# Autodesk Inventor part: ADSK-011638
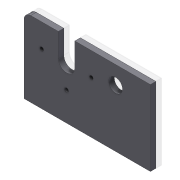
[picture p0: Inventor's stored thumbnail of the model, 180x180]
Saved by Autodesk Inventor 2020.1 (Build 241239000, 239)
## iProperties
Created: 2000-02
Part Number: ADSK-011638
Material: Pearson HRS
Document SubType Name: Modeling
Description: PLT-14,FH,CP,03,090,053,MNT,HANDWHEEL
Designer: cmcgourin
Density: 7.83 g/cm^3
Appearance: Métal - Acier
Mass: 2260.83 g
Surface Area: 675.493 cm^2
Volume: 288.739 cm^3
Control State: 0
Checked Out: False
Master: False
Shininess: 0.0
Length Units: 11269
Angle Units: 11279
Time Units: 11290
Mass Units: 11286
Length Display Precision: 3
Angle Display Precision: 2
Compacted: True
Cutlength: 5.38
Material Desc: FLAT,HRS,0.375X09.000
Material_Number: A084416
Dimensions: 229x136,5x10 mm
Mass: 4,984 lb
Density: 0.0
Volumn: 0.0
Area: 0.0
PropertySet Name: Model Information
Author: cmcgourin
Revision Number: -
Title: PLT-14,FH,CP,03,090,053,MNT,HANDWHEEL
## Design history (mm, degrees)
sketch "Skizze6"
  geometry: L1 (-114.5, 68.25)-(22.5, 68.25) reference; L2 (-114.5, -68.25)-(-114.5, 68.25) reference; C1 r 14 at (-51.5, 35.75); 1 further point
  constraints: 1 centre point
  dimensions: "d36" = 28 diameter of C1; "d37" = 32.5 distance from line of L1 C1.centre; "d38" = 63 distance from line of L2 C1.centre
extrude "Extrusion4" cut sketch "Skizze6" distance "d39" = 10; taper "d40" = 0 deg
node "Solide1"
  node "Extrusion1" dims "d2" = 10, "d3" = 0
  node "Fillet1" dims "d4" = 12
  node "Hole1" dims "d5" = 6.647, "d6" = 9.525, "d7" = 6.35, "d8" = 60 deg, "d9" = 19.05, "d10" = 0, "d31" = 16
  node "Extrusion2" dims "d13" = 25.4, "d14" = 0
sketch "Sketch1"
  geometry: L1 (114.5, 68.25)-(-114.5, 68.25); L2 (-114.5, 68.25)-(-114.5, -68.25); L3 (-114.5, -68.25)-(114.5, -68.25); L4 (114.5, -68.25)-(114.5, 68.25); 3 further points
  constraints: 8 end point, 2 midpoint, 2 parallel, 1 horizontal, 1 horizontal alignment, 1 perpendicular, 1 vertical alignment
  dimensions: "d0" = 229 distance of L2.end L3.end; "d1" = 136.5 distance of L1.end L2.end
sketch "Sketch2"
  geometry: L1 (-82.5, 25.75)-(7.5, 25.75); L2 (-102.5, 68.25)-(114.5, 68.25) reference; L3 (114.5, 68.25)-(114.5, -68.25) reference; 3 further points
  constraints: 2 end point, 1 coincident, 1 horizontal, 1 midpoint, 1 vertical alignment
  dimensions: "d26" = 152 distance from line of L3 point (-37.5, 25.75); "d27" = 90 distance of L1.start L1.end; "d28" = 42.5 distance between parallel lines of L2 L1; "d30" = 42 distance from line of point (-37.5, -16.25) L1
sketch "Sketch4"
  geometry: L1 (-10.865, 36.128)-(-10.865, -53.872); L2 (31.635, -160.872)-(31.635, 56.128) reference; L3 (31.635, 6.128)-(-10.865, 6.128); L4 (-10.865, -23.872)-(31.635, -23.872); C1 r 3.323 at (-10.865, 36.128) reference; C2 r 3.323 at (-10.865, -53.872) reference; A1 r 15 centre (-10.865, -8.872) between (-10.865, 6.128) and (-10.865, -23.872); 1 further point
  constraints: 6 end point, 4 point on line, 2 point on circle, 1 centre point, 1 coincident, 1 horizontal, 1 midpoint, 1 perpendicular, 1 tangent, 1 vertical
  dimensions: "d34" = 30 distance between parallel lines of L3 L4
extrude "Extrusion3" cut sketch "Sketch4" extent not by distance; stored distance "d32" = 0; taper "d33" = 0 deg
sketch "Sketch3"
  geometry: L1 (7.5, 25.75)-(-82.5, 25.75); C1 r 3.572 at (-37.5, -16.25); C2 r 3.324 at (7.5, 25.75) reference; C3 r 3.324 at (-82.5, 25.75) reference; 2 further points
  constraints: 2 end point, 1 centre point, 1 coincident, 1 horizontal, 1 midpoint, 1 vertical alignment
  dimensions: "d12" = 7.14375 diameter of C1; "d35" = 42 distance from line of L1 C1.centre
node "Corps solides"
node "Corps surfaciques"
